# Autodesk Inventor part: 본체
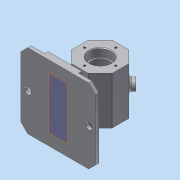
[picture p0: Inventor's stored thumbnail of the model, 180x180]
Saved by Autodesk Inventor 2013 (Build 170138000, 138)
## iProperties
Created: 2018-06
Part Number: 본체
Material: 알루미늄 6061
Document SubType Name: Modeling
Designer: dgall
Density: 2.71 g/cm^3
Mass: 554.7 g
Surface Area: 601.052 cm^2
Volume: 204.686 cm^3
Author: dgall
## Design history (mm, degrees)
sketch "스케치1"
  geometry: L1 (12.426, 30)-(30, 12.426); L2 (30, 12.426)-(30, -12.426); L3 (30, -12.426)-(12.426, -30); L4 (12.426, -30)-(-12.426, -30); L5 (-12.426, -30)-(-30, -12.426); L6 (-30, -12.426)-(-30, 12.426); L7 (-30, 12.426)-(-12.426, 30); L8 (-12.426, 30)-(12.426, 30); L9 (0, 0)-(0, 30); 2 further points
  constraints: 18 end point, 2 coincident, 1 horizontal, 1 midpoint, 17 other
  dimensions: "d2" = 60 distance between parallel lines of L3 L7
extrude "돌출1" new body sketch "스케치1" distance "d3" = 70; taper "d4" = 0 deg
sketch "스케치2"
  geometry: L1 (30, 70)-(30, 0) reference; L2 (30, 0)-(-30, 0) reference; L3 (-30, 0)-(-30, 70) reference; L4 (-30, 70)-(30, 70) reference; L5 (30, 70)-(12.426, 70) reference; L6 (16, 70)-(16, 58); L7 (16, 58)-(14, 58); L8 (12.426, 0)-(12.426, 70) reference; L9 (14, 58)-(14, 55); L10 (14, 55)-(25, 55); L11 (25, 55)-(25, 15); L12 (25, 15)-(14, 15); L13 (14, 15)-(14, 12); L14 (14, 12)-(16, 12); L15 (16, 12)-(16, 0); L16 (16, 70)-(0, 70); L17 (12.426, 70)-(-12.426, 70) reference; L18 (0, 70)-(0, 0); L19 (16, 0)-(0, 0)
  constraints: 24 end point, 7 perpendicular, 3 equal length, 3 parallel, 2 point on line, 1 collinear, 1 midpoint
  dimensions: "d6" = 32 diameter of L6 L18; "d8" = 28 diameter of L9 L18; "d10" = 50 diameter of L11 L18; "d11" = 32 diameter of L15 L18; "d12" = 40 distance of L10.end L11.end; "d13" = 12 distance of L6.start L6.end
revolve "회전1" sketch "스케치2" stored, may be unused: angle "d14" = 90 deg
sketch "스케치3"
  geometry: C1 r 16 at (0, 0) reference; 1 further point
  constraints: 1 vertical alignment
  dimensions: "d15" = 23 distance of C1.centre point (0, 23)
hole "구멍1" sketch "스케치3" at (0, 23) diameter "d16" = 3.242; stored, may be unused: countersink angle "d20" = 90 deg, drill point angle "d22" = 118 deg; dims "d17" = 8, "d18" = 4, "d19" = 2, "d21" = 10
node "작업 평면1"
sketch "스케치4"
  geometry: 1 further point
fillet "모깎기1" dims "d27" = 0.3
fillet "모깎기2" dims "d28" = 3
node "작업 평면2"
sketch "스케치5"
  geometry: L1 (-42.574, -90)-(-42.574, 20); L2 (-42.574, 20)-(67.426, 20); L3 (67.426, 20)-(67.426, -90); L4 (67.426, -90)-(-42.574, -90); L5 (-17.574, 0)-(-17.574, -70) reference; L6 (0, 0)-(24.853, 0) reference; L7 (-12.574, -90)-(-12.574, 20); L8 (37.426, -90)-(37.426, 20); 5 further points
  constraints: 12 end point, 4 midpoint, 4 point on line, 3 perpendicular, 2 parallel, 1 horizontal alignment, 1 vertical, 1 vertical alignment
  dimensions: "d30" = 110 distance of L1.start L1.end; "d32" = 110 distance of L3.end L1.start; "d33" = 30 distance between parallel lines of L1 L7; "d34" = 30 distance between parallel lines of L3 L8
extrude "돌출2" join sketch "스케치5" distance "d35" = 10; taper "d36" = 0 deg
extrude "돌출3" join sketch "스케치5" distance "d37" = 5; taper "d38" = 0 deg
chamfer "모따기1" distance "d39" = 10; stored, may be unused: second distance "d40" = 2, angle "d41" = 45 deg
sketch "스케치8"
  geometry: L1 (-12.574, -90)-(37.426, -90) reference; L2 (-12.574, 20)-(-12.574, -90) reference; L3 (7.426, -54)-(7.426, -16); L4 (17.426, -54)-(17.426, -16); A1 r 5 centre (12.426, -54) between (7.426, -54) and (17.426, -54); A2 r 5 centre (12.426, -16) between (17.426, -16) and (7.426, -16); 2 further points
  constraints: 4 end point, 4 point on circle, 3 parallel, 2 centre point, 2 tangent, 1 midpoint, 1 vertical alignment
  dimensions: "d45" = 5 radius of A1; "d46" = 5 radius of A2; "d47" = 55 distance from line of L1 point (7.426, -35); "d48" = 38 distance of A2.centre A1.centre
extrude "돌출4" join sketch "스케치8" stored distance "d49" = 5; taper "d50" = 0 deg
sketch "스케치9"
  geometry: L1 (0, 0)-(-24.853, 0) reference; L2 (-24.853, 70)-(0, 70) reference; C1 r 8 at (-12.426, 35); C2 r 4 at (-12.426, 35); 2 further points
  constraints: 2 centre point, 1 coincident, 1 midpoint, 1 vertical alignment
  dimensions: "d51" = 35 distance from line of L2 C2.centre; "d52" = 8 diameter of C2; "d53" = 16 diameter of C1
extrude "돌출5" join sketch "스케치9" distance "d54" = 7; taper "d55" = 0 deg
extrude "돌출6" cut sketch "스케치9" stored distance "d56" = 7; taper "d57" = 0 deg
fillet "모깎기3" dims "d58" = 3
chamfer "모따기2" distance "d59" = 1; stored, may be unused: second distance "d60" = 2, angle "d61" = 45 deg
chamfer "모따기3" distance "d62" = 1; stored, may be unused: second distance "d63" = 2, angle "d64" = 45 deg
fillet "모깎기4" dims "d65" = 1
sketch "스케치11"
  geometry: L1 (67.426, -80)-(67.426, 10) reference; L2 (-42.574, 10)-(-42.574, -80) reference; C1 r 5 at (57.426, -35); C2 r 5 at (-32.574, -35); 3 further points
  constraints: 2 centre point, 2 horizontal alignment, 2 midpoint, 1 equal radius
  dimensions: "d67" = 10 diameter of C1; "d69" = 10 distance from line of L1 C1.centre; "d70" = 10 distance from line of L2 C2.centre
extrude "돌출7" cut sketch "스케치11" stored distance "d71" = 7; taper "d72" = 0 deg
sketch "스케치12"
  geometry: L1 (24.024, -70)-(0, -70) reference; L2 (-17.695, -70)-(-17.695, 0) reference; 2 further points
  constraints: 1 other
  dimensions: "d73" = 30 distance from line of point (12.305, -35) L2; "d74" = 35 distance from line of L1 point (12.305, -35)
feature "엠보싱1" sketch "스케치12" dims "d2" = 60, "d6" = 32, "d8" = 28, "d10" = 50, "d11" = 32, "d12" = 40, "d13" = 12, "d75" = 0.5, "d76" = 0
fillet "모깎기6" dims "d77" = 2
node "솔리드1"
pattern_circular "원형 패턴1" dims angle "d24" = 360 deg
mirror "대칭1"
node "절단 모서리 투영1"
other parameters: "d26" = -35, "d29" = -92
